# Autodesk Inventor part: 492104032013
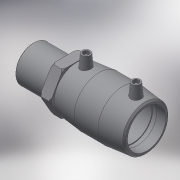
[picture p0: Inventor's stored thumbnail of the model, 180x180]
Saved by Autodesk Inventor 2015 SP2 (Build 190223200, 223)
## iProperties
Created: 2017-06
Part Number: 492104032013
Material: Generic
Description: PLASSON Male Transition Coupler 32 x 1.1/4"
Document SubType Name: Modeling
Designer: KIM
Mass: 98.8463 g
Surface Area: 352.751 cm^2
Volume: 98.8463 cm^3
Density: 1 g/cm^3
Appearance: Default
Author: KIM
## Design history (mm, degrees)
derived "492104.ipt"
feature "Solid1::492104.ipt"
tag "TaggingFeature1"
body "Solid1"
other parameters: "d0" = 88, "d1" = 32, "d2" = 44, "d3" = 42, "d4" = 29.33333, "d5" = 39.6, "d6" = 30.4, "d7" = 32, "d8" = 168 deg, "d10" = 16.8, "d11" = 5.6, "d29" = 42, "d30" = 14, "d31" = 30.8, "d34" = 5 deg, "d41" = 4, "d42" = 14, "d43" = 0, "d48" = 3, "d49" = 0, "d57" = 23, "d58" = 41.91, "d59" = 33.528, "d60" = 32.4, "d61" = 48.4, "d62" = 0.8382, "d65" = 1.32, "d70" = 0.1, "d71" = 36, "d72" = 9, "d73" = 16.8, "d75" = 0, "d_" = 32, "L_" = 124, "L_1" = 42, "D_1" = 44, "A_" = 42, "d_2" = 12, "L_2" = 36, "D_" = 23, "R_" = 41.91
